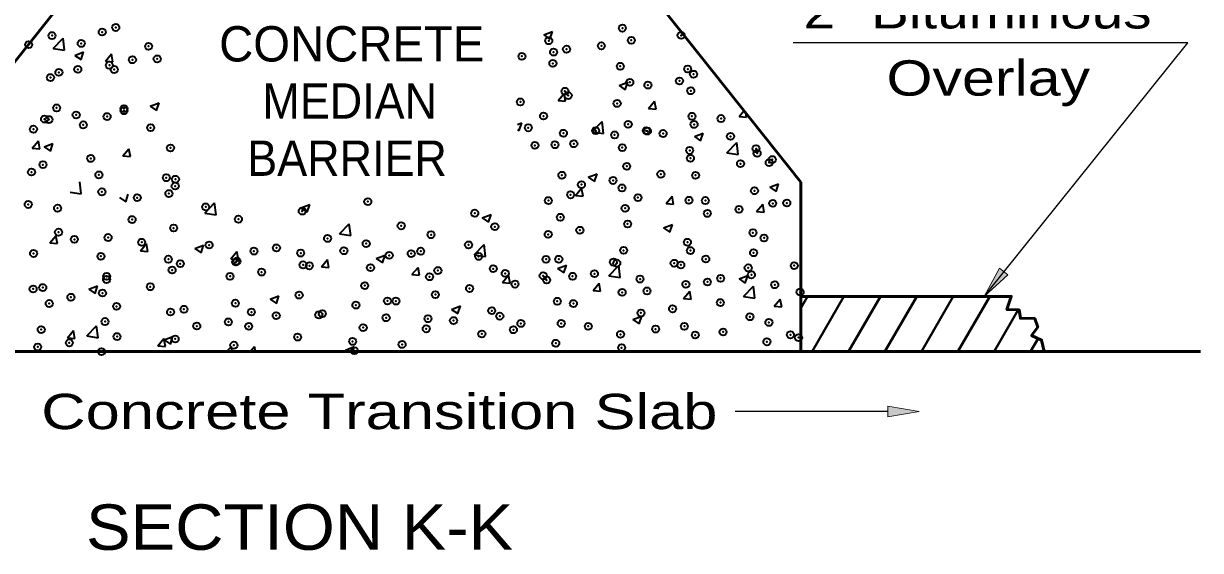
# Model space of a CAD drawing. Extents: x 14 to 49.3, y 28 to 50.
# Drawn here: x 34.953 to 39.615, y 36.094 to 38.182 of the extents above; entities that cross this region are included whole.
import ezdxf

# ---------------------------------------------------------------- set-up
doc = ezdxf.new("R2010")
doc.units = 0
doc.header["$LTSCALE"] = 0.056
doc.header["$PDMODE"] = 32
doc.header["$PDSIZE"] = 0.028
doc.layers.add('1', color=7, linetype='Continuous', lineweight=35)
doc.layers.add('3', color=7, linetype='Continuous', lineweight=13)

msp = doc.modelspace()

# ---------------------------------------------------------------- hatches: boundary and pattern name
at = {"layer": '3'}
for points in [[(38.85208, 37.18592), (38.81925, 37.21175), (38.75833, 37.10067), (38.75833, 37.10067)], [(38.376, 36.6235), (38.376, 36.66525), (38.501, 36.64442), (38.501, 36.64442)]]:
    msp.add_hatch(color=256, dxfattribs=at).paths.add_polyline_path(points)

# ---------------------------------------------------------------- linework, layer by layer
at = {"layer": '1', "lineweight": 53}
for p, q in [((34.53892, 37.553), (35.13542, 38.30408)), ((38.0315, 36.88158), (39.61483, 36.88158))]:
    msp.add_line(p, q, dxfattribs=at)
at = {"layer": '1'}
for p, q in [((37.01325, 38.13675), (37.04825, 38.15025)), ((37.01325, 38.13675), (37.03817, 38.12)), ((37.03817, 38.12), (37.04833, 38.15017)), ((35.07092, 38.08333), (35.10992, 38.12392)), ((35.11542, 38.07642), (35.10992, 38.12392)), ((35.07092, 38.08333), (35.11542, 38.07642)), ((35.156, 38.05558), (35.19108, 38.069)), ((35.156, 38.05558), (35.18092, 38.03883)), ((35.18092, 38.03883), (35.19108, 38.069)), ((35.27692, 38.033), (35.30108, 38.06175)), ((35.30683, 38.03033), (35.30108, 38.06167)), ((35.27692, 38.033), (35.30683, 38.03033)), ((37.31175, 37.9355), (37.34675, 37.94892)), ((37.33658, 37.91867), (37.34675, 37.94892)), ((37.07008, 37.87608), (37.09417, 37.90483)), ((37.1, 37.8735), (37.09425, 37.90483)), ((37.31175, 37.9355), (37.33658, 37.91867)), ((35.4545, 37.85425), (35.4895, 37.86775)), ((35.47933, 37.8375), (35.4895, 37.86767)), ((37.07008, 37.87608), (37.1, 37.8735)), ((37.42875, 37.84475), (37.45283, 37.87342)), ((37.45858, 37.84208), (37.45283, 37.87342)), ((35.4545, 37.85425), (35.47933, 37.8375)), ((37.42875, 37.84475), (37.45858, 37.84208)), ((37.78733, 37.81333), (37.8065, 37.83617)), ((37.78733, 37.81333), (37.81725, 37.81075)), ((37.81725, 37.81075), (37.81433, 37.82633)), ((36.90942, 37.781), (36.92667, 37.78767)), ((36.90942, 37.76217), (36.9165, 37.75742)), ((36.9165, 37.75742), (36.92667, 37.78758)), ((37.20542, 37.75233), (37.24433, 37.79292)), ((37.24992, 37.74542), (37.24433, 37.79292)), ((34.98767, 37.68825), (35.01183, 37.717)), ((35.01758, 37.68567), (35.01183, 37.717)), ((37.20542, 37.75233), (37.24992, 37.74542)), ((37.61017, 37.73417), (37.64517, 37.74758)), ((37.61017, 37.73417), (37.63508, 37.71742)), ((37.63508, 37.71733), (37.64517, 37.74758)), ((34.98767, 37.68825), (35.01758, 37.68567)), ((35.03442, 37.693), (35.06942, 37.7065)), ((35.03442, 37.693), (35.05925, 37.67625)), ((35.05925, 37.67625), (35.06942, 37.70642)), ((35.34633, 37.65692), (35.37042, 37.68558)), ((35.37625, 37.65425), (35.37042, 37.68558)), ((37.73908, 37.66958), (37.778, 37.71017)), ((37.73908, 37.66958), (37.7835, 37.66267)), ((37.7835, 37.66267), (37.778, 37.71008)), ((35.34633, 37.65692), (35.37625, 37.65425)), ((37.19008, 37.57292), (37.22508, 37.58633)), ((37.21492, 37.55608), (37.22508, 37.58633)), ((35.18167, 37.50658), (35.17617, 37.55408)), ((37.1395, 37.5), (37.16358, 37.52875)), ((37.16933, 37.49742), (37.16358, 37.52875)), ((37.19008, 37.57292), (37.21492, 37.55608)), ((37.90867, 37.53283), (37.94367, 37.54625)), ((37.90867, 37.53283), (37.9335, 37.51608)), ((37.9335, 37.51608), (37.94367, 37.54625)), ((35.13725, 37.5135), (35.18167, 37.50667)), ((35.33283, 37.49175), (35.35767, 37.47492)), ((35.35775, 37.47492), (35.36783, 37.50517)), ((37.1395, 37.5), (37.16933, 37.49742)), ((37.49808, 37.46867), (37.52225, 37.49733)), ((37.528, 37.466), (37.52225, 37.49733)), ((35.67083, 37.43075), (35.70983, 37.47133)), ((35.71533, 37.42383), (35.70983, 37.47133)), ((36.05142, 37.45167), (36.08642, 37.46508)), ((36.05142, 37.45167), (36.07625, 37.43492)), ((36.07625, 37.43483), (36.08642, 37.46508)), ((37.49808, 37.46867), (37.528, 37.466)), ((37.85675, 37.43725), (37.88083, 37.466)), ((37.85675, 37.43725), (37.88658, 37.43467)), ((37.88667, 37.43458), (37.88083, 37.466)), ((35.67083, 37.43075), (35.71533, 37.42383)), ((36.2045, 37.348), (36.24342, 37.38858)), ((36.24892, 37.34108), (36.24342, 37.38858)), ((36.77, 37.41158), (36.805, 37.42508)), ((36.77, 37.41158), (36.79483, 37.39483)), ((36.79483, 37.39483), (36.805, 37.42508)), ((36.2045, 37.348), (36.24892, 37.34108)), ((37.4885, 37.37158), (37.5235, 37.385)), ((37.4885, 37.37158), (37.51342, 37.35483)), ((37.51342, 37.35475), (37.52358, 37.385)), ((35.05708, 37.31217), (35.08117, 37.34092)), ((35.05708, 37.31217), (35.08692, 37.30958)), ((35.087, 37.3095), (35.08117, 37.34092)), ((35.41567, 37.28083), (35.43983, 37.3095)), ((35.44558, 37.27817), (35.43983, 37.3095)), ((35.63125, 37.29042), (35.66633, 37.30383)), ((35.65617, 37.27358), (35.66633, 37.30383)), ((36.73808, 37.26525), (36.777, 37.30583)), ((36.78258, 37.25833), (36.77708, 37.30583)), ((35.41567, 37.28083), (35.44558, 37.27817)), ((35.63125, 37.29042), (35.65617, 37.27367)), ((35.77433, 37.24942), (35.79842, 37.27817)), ((35.77433, 37.24942), (35.80425, 37.24683)), ((35.80425, 37.24675), (35.79842, 37.27817)), ((36.34983, 37.25033), (36.38483, 37.26383)), ((36.34983, 37.25033), (36.37475, 37.23358)), ((36.37475, 37.23358), (36.38483, 37.26375)), ((36.73808, 37.26525), (36.78258, 37.25833)), ((36.133, 37.218), (36.15708, 37.24675)), ((36.133, 37.218), (36.16283, 37.21542)), ((36.16283, 37.21542), (36.15708, 37.24675)), ((36.49158, 37.18667), (36.51567, 37.21542)), ((36.5215, 37.184), (36.51567, 37.21533)), ((37.06842, 37.21033), (37.10342, 37.22375)), ((37.06842, 37.21033), (37.09325, 37.1935)), ((37.09333, 37.1935), (37.10342, 37.22375)), ((37.27175, 37.1825), (37.31067, 37.22308)), ((37.31617, 37.17558), (37.31067, 37.22308)), ((36.49158, 37.18667), (36.5215, 37.18408)), ((36.85025, 37.15525), (36.87433, 37.184)), ((36.88008, 37.15267), (36.87433, 37.184)), ((37.27175, 37.1825), (37.31617, 37.17558)), ((37.787, 37.17025), (37.822, 37.18375)), ((37.787, 37.17025), (37.81183, 37.1535)), ((37.81183, 37.1535), (37.822, 37.18367)), ((35.21117, 37.12917), (35.24617, 37.14258)), ((35.21117, 37.12917), (35.23608, 37.11233)), ((35.23608, 37.11233), (35.24617, 37.14258)), ((36.85025, 37.15525), (36.88008, 37.15267)), ((37.20883, 37.12392), (37.23292, 37.15267)), ((37.20883, 37.12392), (37.23875, 37.12133)), ((37.23875, 37.12125), (37.233, 37.15258)), ((37.5675, 37.0925), (37.59158, 37.12125)), ((37.59733, 37.08992), (37.59158, 37.12125)), ((37.80533, 37.09975), (37.84425, 37.14033)), ((37.84983, 37.09283), (37.84425, 37.14033)), ((35.92975, 37.08908), (35.96475, 37.1025)), ((35.92975, 37.08908), (35.95458, 37.07233)), ((35.95458, 37.07233), (35.96475, 37.1025)), ((36.64833, 37.04908), (36.68333, 37.0625)), ((36.67317, 37.03225), (36.68333, 37.0625)), ((37.5675, 37.0925), (37.59733, 37.08992)), ((37.80533, 37.09975), (37.84983, 37.09283)), ((37.92608, 37.06117), (37.95025, 37.08992)), ((37.956, 37.0585), (37.95025, 37.08983)), ((36.64833, 37.04908), (36.67317, 37.03225)), ((37.36683, 37.009), (37.40192, 37.02242)), ((37.39175, 36.99225), (37.40192, 37.02242)), ((37.92608, 37.06117), (37.956, 37.05858)), ((35.2035, 36.94367), (35.2425, 36.98433)), ((35.248, 36.93683), (35.2425, 36.98425)), ((37.36683, 37.009), (37.39175, 36.99225)), ((35.12642, 36.93608), (35.15058, 36.96483)), ((35.12642, 36.93608), (35.15633, 36.9335)), ((35.15633, 36.93342), (35.15058, 36.96475)), ((35.2035, 36.94367), (35.248, 36.93683)), ((35.48508, 36.90467), (35.50917, 36.93342)), ((35.515, 36.90208), (35.50917, 36.93342)), ((35.50967, 36.92783), (35.54467, 36.94125)), ((35.50967, 36.92783), (35.54467, 36.94125)), ((35.50967, 36.92783), (35.5345, 36.91108)), ((35.5345, 36.911), (35.54467, 36.94125)), ((35.48508, 36.90467), (35.515, 36.90208)), ((35.75692, 36.88158), (35.77608, 36.9015)), ((35.77842, 36.88158), (35.77608, 36.9015)), ((35.85058, 36.88158), (35.86783, 36.90208)), ((35.87158, 36.88158), (35.86783, 36.902)), ((36.22817, 36.88775), (36.26317, 36.90125)), ((36.22817, 36.88775), (36.23742, 36.88158)), ((36.25658, 36.88158), (36.26325, 36.90117))]:
    msp.add_line(p, q, dxfattribs=at)
at = {"layer": '1', "lineweight": 40}
for p, q in [((38.0315, 37.054), (38.05842, 37.10067)), ((38.07625, 36.88158), (38.20275, 37.10067)), ((38.22058, 36.88158), (38.34708, 37.10067)), ((38.36492, 36.88158), (38.49142, 37.10067)), ((38.50925, 36.88158), (38.63575, 37.10067)), ((38.65358, 36.88158), (38.78008, 37.10067)), ((38.79792, 36.88158), (38.89325, 37.04667)), ((38.94225, 36.88158), (38.97233, 36.93367))]:
    msp.add_line(p, q, dxfattribs=at)
at = {"layer": '1', "lineweight": 53}
for points in [[(38.0315, 37.553), (37.43492, 38.30408), (37.15292, 38.88442), (37.04442, 39.51033), (36.90675, 40.80042)], [(38.99583, 36.88158), (38.98575, 36.92758), (38.94617, 36.94558), (38.97025, 36.97808), (38.95825, 37.01233), (38.9015, 37.01408), (38.89633, 37.04658), (38.84825, 37.04842), (38.86542, 37.10067), (38.0315, 37.10067), (38.0315, 37.553)], [(34.53892, 37.34817), (34.53892, 36.88158), (38.0315, 36.88158), (38.0315, 37.10067)]]:
    msp.add_lwpolyline(points, dxfattribs=at)
at = {"layer": '1'}
for p in [(35.06567, 38.134), (35.26467, 38.14792), (35.31817, 38.166), (37.325, 38.16342), (37.5575, 38.13492), (34.97308, 38.09783), (35.18142, 38.10283), (35.44833, 38.09158), (37.03342, 38.11342), (37.10367, 38.08), (37.24175, 38.09333), (37.36042, 38.11517), (35.3845, 38.03808), (35.48233, 38.04158), (36.92717, 38.05192), (37.05233, 38.06842), (35.09292, 37.98808), (35.16775, 38.00017), (35.29292, 38.01667), (35.31217, 37.9995), (37.04983, 38.02392), (37.31675, 38.01258), (37.58367, 38.00133), (37.60683, 37.98075), (35.05958, 37.9675), (37.35433, 37.94875), (37.426, 37.93775), (37.55117, 37.95417), (37.09758, 37.9135), (37.11017, 37.89617), (37.59592, 37.91517), (35.08408, 37.84733), (35.35075, 37.84442), (36.92083, 37.87125), (37.30433, 37.86508), (35.03625, 37.803), (35.0535, 37.80108), (35.16142, 37.8195), (35.28383, 37.81308), (35.351, 37.83608), (37.01275, 37.81508), (37.60075, 37.81433), (37.71575, 37.80533), (34.99225, 37.763), (35.1895, 37.78017), (35.45642, 37.76892), (36.95242, 37.76842), (37.21933, 37.75708), (37.34825, 37.78233), (37.41958, 37.757), (37.42417, 37.75533), (37.609, 37.78192), (37.05783, 37.70125), (37.0915, 37.74708), (37.13258, 37.70525), (37.29442, 37.7405), (37.48625, 37.74583), (37.75317, 37.73458), (35.535, 37.68875), (36.97867, 37.69892), (37.32475, 37.68992), (37.59167, 37.67867), (37.85442, 37.68533), (37.85858, 37.66742), (35.02992, 37.62225), (35.21925, 37.64717), (37.34217, 37.61583), (37.59467, 37.64783), (37.79317, 37.62625), (37.90667, 37.63042), (37.91833, 37.64275), (34.98458, 37.59317), (35.2515, 37.58192), (35.51842, 37.57058), (35.55475, 37.56475), (37.08542, 37.58067), (37.47742, 37.58475), (37.61508, 37.58033), (35.26317, 37.51475), (35.55358, 37.53767), (37.16292, 37.54333), (37.28808, 37.55975), (37.3235, 37.53033), (37.84833, 37.51892), (35.4035, 37.49158), (35.52867, 37.508), (36.3165, 37.47592), (37.03192, 37.48025), (37.11992, 37.50292), (37.38675, 37.49167), (37.58858, 37.48142), (37.65367, 37.48042), (37.92058, 37.46908), (37.97617, 37.4705), (34.97158, 37.46467), (35.08775, 37.45), (35.67458, 37.455), (36.05675, 37.43842), (36.74033, 37.43017), (37.33608, 37.44942), (37.66167, 37.42908), (37.78683, 37.44558), (35.383, 37.40492), (35.80425, 37.40642), (36.44875, 37.38017), (36.81967, 37.37667), (37.07933, 37.41417), (37.34592, 37.3875), (35.09142, 37.35492), (35.28783, 37.33375), (35.5475, 37.37125), (36.15717, 37.33008), (36.56708, 37.34467), (37.03133, 37.34608), (37.1565, 37.36258), (37.84225, 37.35242), (37.88608, 37.33208), (35.15417, 37.32642), (35.42108, 37.31508), (35.68792, 37.30383), (35.95483, 37.29258), (36.31042, 37.3095), (36.71558, 37.3045), (37.33, 37.28292), (37.58258, 37.315), (37.5945, 37.282), (34.99267, 37.2705), (35.25958, 37.25925), (35.5265, 37.24792), (35.79342, 37.23667), (35.79817, 37.24), (35.86558, 37.28), (36.05067, 37.272), (36.22175, 37.28125), (36.40108, 37.26308), (36.48867, 37.27), (36.52625, 37.27958), (36.75558, 37.25875), (37.0225, 37.24742), (37.07325, 37.24775), (37.28942, 37.23617), (37.65533, 37.24833), (37.84467, 37.27325), (35.54142, 37.20475), (35.57392, 37.23), (35.89592, 37.19658), (36.06025, 37.22542), (36.08525, 37.22158), (36.32717, 37.21417), (36.59408, 37.20283), (36.81358, 37.21025), (36.861, 37.19158), (37.21433, 37.19033), (37.30283, 37.232), (37.53017, 37.23183), (37.55633, 37.22492), (37.82325, 37.21358), (38.00583, 37.22225), (35.28175, 37.16733), (35.28233, 37.17992), (35.77075, 37.18017), (36.30433, 37.14308), (36.561, 37.17825), (36.89983, 37.14892), (37.01125, 37.18192), (37.025, 37.16533), (37.12792, 37.18033), (37.39483, 37.169), (37.5765, 37.1485), (37.66175, 37.15775), (37.71425, 37.17225), (37.83617, 37.186), (37.92867, 37.1465), (34.99075, 37.12983), (35.02917, 37.13533), (35.14042, 37.09717), (35.26558, 37.11367), (35.455, 37.13858), (36.04458, 37.10558), (36.58408, 37.10733), (36.71967, 37.13183), (37.32392, 37.1165), (37.42267, 37.12217), (38.02892, 37.11767), (35.05467, 37.07225), (35.32158, 37.061), (35.5885, 37.04967), (35.79208, 37.07358), (36.2695, 37.06592), (36.39467, 37.08242), (36.42808, 37.08183), (37.06717, 37.08133), (37.13108, 37.07208), (37.52375, 37.05117), (37.71317, 37.07608), (35.53533, 37.03833), (35.85542, 37.03842), (35.95375, 37.02433), (36.12233, 37.02717), (36.1365, 37.03175), (36.38925, 37.01583), (36.55492, 37.01183), (36.65617, 37.00458), (36.8075, 37.04383), (36.8395, 37.02208), (37.39858, 37.03467), (37.83008, 37.01958), (35.02308, 36.96883), (35.27567, 37.00083), (35.63917, 36.98292), (35.76433, 36.99942), (35.84492, 36.98167), (36.29825, 36.97658), (36.54792, 36.972), (36.8935, 36.96817), (36.923, 36.99333), (37.08283, 36.99308), (37.18992, 36.982), (37.45683, 36.97075), (37.57042, 36.98208), (37.72375, 36.9595), (37.90525, 36.99725), (35.13408, 36.91642), (35.32342, 36.94133), (35.55333, 36.93167), (36.0385, 36.93908), (36.25633, 36.922), (36.4525, 36.91008), (36.76825, 36.95167), (37.06108, 36.91483), (37.31783, 36.95008), (37.61367, 36.94717), (37.89742, 36.92042), (37.99067, 36.94817), (38.02258, 36.93692), (35.00892, 36.89992), (35.26175, 36.88158), (35.786, 36.90708), (36.26317, 36.88517), (37.322, 36.89717)]:
    msp.add_point(p, dxfattribs=at)
at = {"layer": '3', "lineweight": 25}
for p, q in [((39.56433, 38.10533), (38.00142, 38.10533)), ((38.75833, 37.10067), (39.56433, 38.10533)), ((38.376, 36.64442), (37.77217, 36.64442))]:
    msp.add_line(p, q, dxfattribs=at)
at = {"layer": '3'}
for points in [[(38.85208, 37.18592), (38.81925, 37.21175), (38.75833, 37.10067), (38.75833, 37.10067)], [(38.376, 36.6235), (38.376, 36.66525), (38.501, 36.64442), (38.501, 36.64442)]]:
    msp.add_lwpolyline(points, close=True, dxfattribs=at)

# ---------------------------------------------------------------- texts
for s, height, width, p in [('2" Bituminous', 0.14, 1.2, (38.04275, 38.16217)), ('Overlay', 0.14, 1.25, (38.37125, 37.89592)), ('MEDIAN', 0.14, 0.95, (35.89917, 37.80458)), ('BARRIER', 0.14, 0.95, (35.83917, 37.578)), ('Concrete Transition Slab', 0.14, 1.3, (35.02308, 36.57442)), ('SECTION K-K', 0.18, 1.1, (35.20042, 36.09617))]:
    msp.add_text(s, height=height, dxfattribs=dict(at, width=width)).set_placement(p)
msp.add_text('CONCRETE', height=0.14, dxfattribs=at).set_placement((35.72775, 38.03125))

doc.saveas('drawing.dxf')
